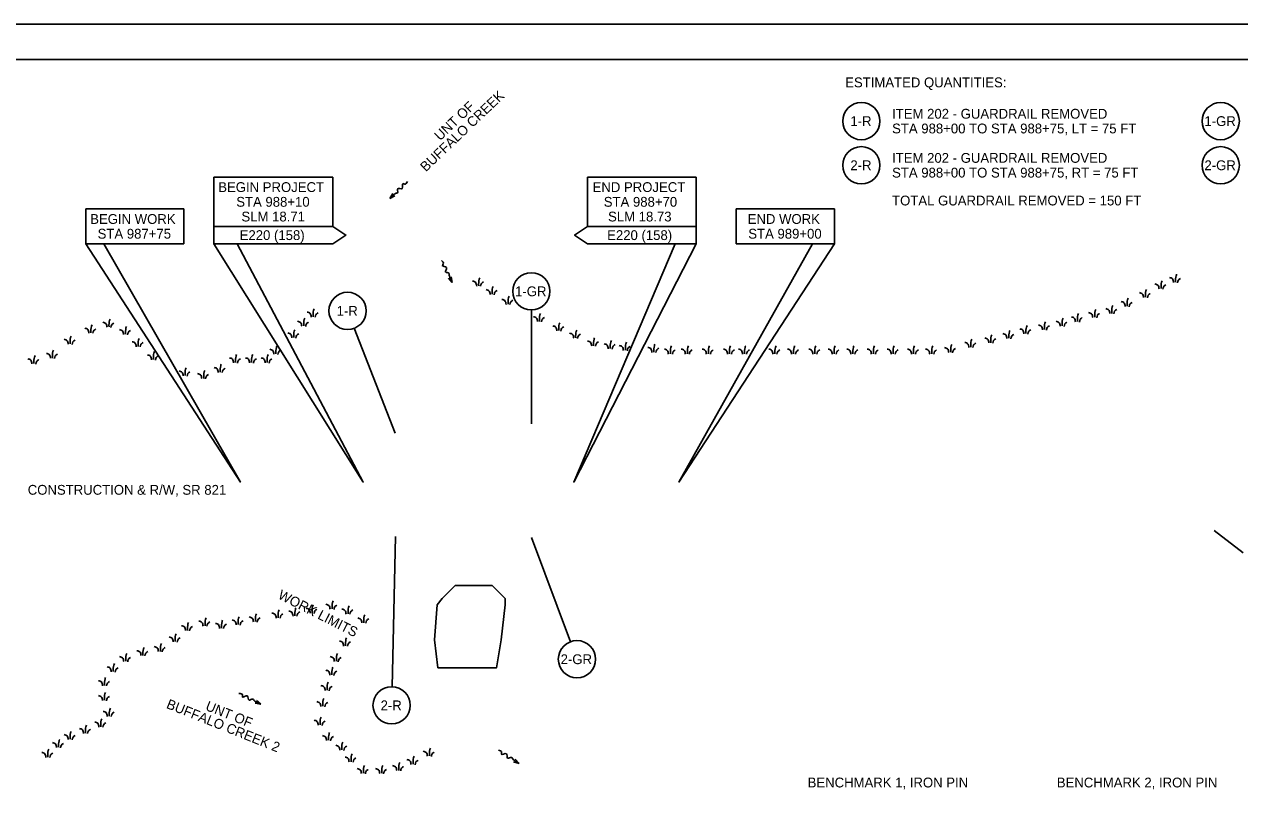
# Model space of a CAD drawing. Extents: x 0 to 905, y 0 to 440.
# Drawn here: x 207.4 to 553.9, y 221.7 to 440 of the extents above; entities that cross this region are included whole.
import ezdxf

# ---------------------------------------------------------------- set-up
doc = ezdxf.new("R2010")
doc.units = 0
for name, color, linetype in [('DR_X_Culvert', 7, 'Continuous'), ('DT_P_Slope_Break_Line', 7, 'Continuous'), ('GE_X_Alignment', 7, 'Continuous'), ('GE_X_Alignment_100_Cardinal_Points', 7, 'Continuous'), ('PF_X_Ground_Line', 7, 'Continuous'), ('PV_P_EOP', 7, 'Continuous'), ('TX_X_20', 7, 'Continuous')]:
    doc.layers.add(name, color=color, linetype=linetype)

msp = doc.modelspace()

# ---------------------------------------------------------------- linework, layer by layer
at = {"layer": 'DR_X_Culvert'}
msp.add_lwpolyline([(0, 0), (680, 0), (680, 440), (0, 440)], close=True, dxfattribs=at)
at = {"layer": 'DT_P_Slope_Break_Line'}
for p, q in [((312.42, 391.7), (311.58, 390.28)), ((311.58, 390.28), (313.02, 391.09)), ((328.3, 367.57), (329.37, 366.31)), ((329.37, 366.31), (329.07, 367.94)), ((273.21, 246.36), (274.84, 246.04)), ((274.84, 246.04), (273.59, 247.13)), ((346.85, 229.65), (348.43, 229.15)), ((348.43, 229.15), (347.31, 230.37))]:
    msp.add_line(p, q, dxfattribs=at)
for points in [[(311.58, 390.28), (312.77, 391.43), (313.35, 391.79), (313.75, 391.97), (313.84, 393.09), (315.11, 393.18), (315.34, 394.55), (315.81, 394.39), (316.59, 395.17)], [(329.37, 366.31), (328.66, 367.81), (328.51, 368.47), (328.46, 368.91), (327.43, 369.36), (327.76, 370.59), (326.53, 371.24), (326.83, 371.64), (326.35, 372.63)], [(274.84, 246.04), (273.35, 246.78), (272.83, 247.2), (272.52, 247.52), (271.43, 247.24), (270.93, 248.41), (269.56, 248.16), (269.55, 248.66), (268.56, 249.14)], [(348.43, 229.15), (347.03, 230.05), (346.56, 230.53), (346.28, 230.87), (345.17, 230.71), (344.8, 231.93), (343.41, 231.83), (343.46, 232.33), (342.53, 232.91)]]:
    msp.add_spline(points, degree=3, dxfattribs=at)
at = {"layer": 'GE_X_Alignment'}
for p, q in [((261.37, 377.36), (261.37, 396.36)), ((261.37, 396.36), (295.37, 396.36)), ((295.37, 382.36), (295.37, 396.36)), ((367.95, 382.36), (367.95, 396.36)), ((398.95, 396.36), (367.95, 396.36)), ((398.95, 377.36), (398.95, 396.36)), ((224.87, 377.36), (224.87, 387.36)), ((224.87, 387.36), (252.87, 387.36)), ((252.87, 377.36), (252.87, 387.36)), ((410.37, 377.36), (410.37, 387.36)), ((410.37, 387.36), (438.37, 387.36)), ((438.37, 377.36), (438.37, 387.36)), ((261.37, 382.36), (295.37, 382.36)), ((398.95, 382.36), (367.95, 382.36)), ((224.87, 377.36), (252.87, 377.36)), ((261.37, 377.36), (295.37, 377.36)), ((398.95, 377.36), (367.95, 377.36)), ((410.37, 377.36), (438.37, 377.36)), ((546.66, 295.61), (554.87, 289.22))]:
    msp.add_line(p, q, dxfattribs=at)
for points in [[(295.37, 382.36), (299.06, 379.86), (295.37, 377.36)], [(367.95, 382.36), (364.26, 379.86), (367.95, 377.36)], [(224.87, 377.36), (269, 309.44), (230.07, 377.36)], [(261.37, 377.36), (304, 309.44), (268.08, 377.36)], [(398.95, 377.36), (364, 309.44), (392.96, 377.36)], [(438.37, 377.36), (394, 309.44), (432.1, 377.36)]]:
    msp.add_lwpolyline(points, dxfattribs=at)
for centre in [(446.03, 412.38), (548.5, 412.38), (446.03, 399.79), (548.5, 399.79), (351.93, 363.83), (299.53, 358.25), (364.93, 258.89), (312.08, 245.73)]:
    msp.add_circle(centre, 5.31, dxfattribs=at)
at = {"layer": 'GE_X_Alignment_100_Cardinal_Points'}
for p, q in [((351.93, 326.04), (351.93, 358.52)), ((301.45, 353.31), (313.06, 323.4)), ((312.2, 251.04), (313.22, 293.94)), ((363.07, 263.86), (351.98, 293.64))]:
    msp.add_line(p, q, dxfattribs=at)
at = {"layer": 'PF_X_Ground_Line'}
msp.add_lwpolyline([(30, 430), (670, 430), (670, 10), (30, 10)], close=True, dxfattribs=at)
at = {"layer": 'PV_P_EOP'}
msp.add_lwpolyline([(325.29, 256.44), (342.02, 256.44), (343.29, 264.44), (344.42, 274.44), (344.49, 276.19), (340.75, 279.94), (330.25, 279.94), (326.51, 276.19), (325.08, 274.44), (324.31, 264.44), (325.29, 256.44)], close=True, dxfattribs=at)
at = {"layer": 'TX_X_20'}
for points in [[(336.91, 365.42), (336.91, 366.37), (337.02, 367.26), (337.2, 367.67)], [(533.89, 367.77), (534.72, 367.42), (535.07, 366.35)], [(535.64, 366.43), (535.64, 367.38), (535.76, 368.27), (535.93, 368.68)], [(536.19, 366.29), (536.43, 367.06), (537.02, 367.53)], [(335.16, 366.76), (335.99, 366.41), (336.34, 365.34)], [(337.46, 365.28), (337.7, 366.05), (338.29, 366.52)], [(339.03, 364.34), (339.85, 363.99), (340.21, 362.92)], [(340.77, 363), (340.77, 363.95), (340.89, 364.84), (341.07, 365.25)], [(341.33, 362.86), (341.56, 363.63), (342.15, 364.1)], [(527.04, 362.13), (527.04, 363.08), (527.16, 363.96), (527.33, 364.38)], [(529.73, 365.94), (530.56, 365.58), (530.92, 364.52)], [(531.48, 364.6), (531.48, 365.54), (531.6, 366.43), (531.77, 366.85)], [(532.03, 364.45), (532.27, 365.22), (532.86, 365.7)], [(343.54, 361.52), (344.36, 361.17), (344.72, 360.1)], [(345.28, 360.18), (345.28, 361.13), (345.4, 362.02), (345.58, 362.43)], [(345.84, 360.04), (346.07, 360.81), (346.66, 361.28)], [(520.08, 360.93), (520.91, 360.58), (521.26, 359.51)], [(521.82, 359.59), (521.82, 360.54), (521.94, 361.42), (522.12, 361.84)], [(522.38, 359.45), (522.62, 360.21), (523.21, 360.69)], [(525.29, 363.47), (526.12, 363.12), (526.48, 362.05)], [(527.59, 361.99), (527.83, 362.75), (528.42, 363.23)], [(287.99, 357.91), (288.81, 357.56), (289.17, 356.49)], [(289.73, 356.57), (289.73, 357.52), (289.85, 358.4), (290.03, 358.82)], [(290.29, 356.43), (290.52, 357.19), (291.11, 357.67)], [(354.26, 355.26), (354.26, 356.21), (354.38, 357.1), (354.56, 357.51)], [(507.65, 355.23), (507.65, 356.17), (507.77, 357.06), (507.94, 357.48)], [(510.83, 357.76), (511.66, 357.41), (512.02, 356.34)], [(512.58, 356.42), (512.58, 357.37), (512.7, 358.26), (512.88, 358.67)], [(513.14, 356.28), (513.37, 357.05), (513.96, 357.52)], [(515.7, 358.89), (516.53, 358.54), (516.88, 357.47)], [(517.44, 357.55), (517.44, 358.5), (517.56, 359.39), (517.74, 359.8)], [(518, 357.41), (518.24, 358.18), (518.83, 358.65)], [(226.37, 351.99), (226.37, 352.94), (226.48, 353.82), (226.66, 354.24)], [(229.76, 355.02), (230.59, 354.67), (230.95, 353.6)], [(231.51, 353.68), (231.51, 354.63), (231.63, 355.52), (231.81, 355.93)], [(232.07, 353.54), (232.3, 354.31), (232.89, 354.78)], [(236.23, 351.57), (236.23, 352.51), (236.35, 353.4), (236.53, 353.82)], [(285.29, 355.29), (286.12, 354.94), (286.47, 353.87)], [(287.03, 353.95), (287.03, 354.9), (287.15, 355.78), (287.33, 356.2)], [(287.59, 353.81), (287.83, 354.57), (288.42, 355.05)], [(352.52, 356.6), (353.35, 356.25), (353.7, 355.18)], [(354.82, 355.12), (355.06, 355.89), (355.65, 356.36)], [(358.04, 353.98), (358.86, 353.63), (359.22, 352.56)], [(359.78, 352.64), (359.78, 353.59), (359.9, 354.48), (360.08, 354.89)], [(360.34, 352.5), (360.57, 353.27), (361.16, 353.74)], [(492.96, 351.79), (492.96, 352.74), (493.08, 353.63), (493.26, 354.04)], [(496.5, 354.26), (497.33, 353.91), (497.68, 352.84)], [(498.25, 352.92), (498.25, 353.87), (498.37, 354.75), (498.54, 355.17)], [(498.8, 352.78), (499.04, 353.54), (499.63, 354.02)], [(501.53, 355.3), (502.36, 354.94), (502.71, 353.88)], [(503.28, 353.96), (503.28, 354.9), (503.4, 355.79), (503.57, 356.21)], [(503.83, 353.81), (504.07, 354.58), (504.66, 355.06)], [(505.9, 356.57), (506.73, 356.21), (507.08, 355.15)], [(508.2, 355.08), (508.44, 355.85), (509.03, 356.33)], [(218.7, 350.15), (219.53, 349.8), (219.88, 348.73)], [(220.45, 348.81), (220.45, 349.76), (220.56, 350.65), (220.74, 351.06)], [(224.62, 353.33), (225.45, 352.98), (225.8, 351.91)], [(226.92, 351.85), (227.16, 352.61), (227.75, 353.09)], [(234.49, 352.91), (235.32, 352.55), (235.67, 351.49)], [(236.79, 351.42), (237.03, 352.19), (237.62, 352.67)], [(239.83, 348.11), (239.83, 349.06), (239.95, 349.94), (240.12, 350.36)], [(282.47, 351.98), (283.3, 351.63), (283.65, 350.56)], [(284.22, 350.64), (284.22, 351.59), (284.33, 352.48), (284.51, 352.89)], [(284.77, 350.5), (285.01, 351.27), (285.6, 351.74)], [(362.83, 351.89), (363.66, 351.54), (364.01, 350.47)], [(364.57, 350.55), (364.57, 351.5), (364.69, 352.38), (364.87, 352.8)], [(365.13, 350.41), (365.37, 351.17), (365.96, 351.65)], [(369.69, 348.33), (369.69, 349.28), (369.81, 350.17), (369.98, 350.58)], [(477.24, 347.91), (477.24, 348.86), (477.36, 349.75), (477.54, 350.16)], [(481.21, 350.52), (482.03, 350.17), (482.39, 349.1)], [(482.95, 349.18), (482.95, 350.13), (483.07, 351.02), (483.25, 351.43)], [(483.51, 349.04), (483.74, 349.81), (484.33, 350.28)], [(486.35, 351.79), (487.18, 351.44), (487.53, 350.37)], [(488.1, 350.45), (488.1, 351.4), (488.22, 352.29), (488.39, 352.7)], [(488.65, 350.31), (488.89, 351.08), (489.48, 351.55)], [(491.21, 353.13), (492.04, 352.78), (492.4, 351.71)], [(493.52, 351.65), (493.75, 352.42), (494.34, 352.89)], [(215.4, 344.8), (215.4, 345.74), (215.52, 346.63), (215.69, 347.05)], [(221, 348.67), (221.24, 349.44), (221.83, 349.91)], [(238.08, 349.45), (238.91, 349.1), (239.26, 348.03)], [(240.38, 347.97), (240.62, 348.73), (241.21, 349.21)], [(244.2, 344.37), (244.2, 345.32), (244.32, 346.21), (244.49, 346.62)], [(277.35, 347.31), (278.18, 346.95), (278.54, 345.89)], [(279.1, 345.97), (279.1, 346.91), (279.22, 347.8), (279.4, 348.22)], [(279.66, 345.82), (279.89, 346.59), (280.48, 347.07)], [(367.94, 349.67), (368.77, 349.32), (369.13, 348.25)], [(370.24, 348.19), (370.48, 348.96), (371.07, 349.43)], [(372.7, 348.87), (373.52, 348.51), (373.88, 347.45)], [(374.44, 347.53), (374.44, 348.47), (374.56, 349.36), (374.74, 349.78)], [(375, 347.38), (375.23, 348.15), (375.82, 348.63)], [(377, 348.38), (377.83, 348.03), (378.19, 346.96)], [(378.75, 347.04), (378.75, 347.99), (378.87, 348.88), (379.05, 349.29)], [(379.31, 346.9), (379.54, 347.67), (380.13, 348.14)], [(385.14, 347.83), (385.97, 347.48), (386.32, 346.41)], [(386.88, 346.49), (386.88, 347.44), (387, 348.33), (387.18, 348.74)], [(387.44, 346.35), (387.68, 347.12), (388.27, 347.59)], [(389.85, 347.35), (390.68, 346.99), (391.03, 345.93)], [(391.6, 346.01), (391.6, 346.95), (391.72, 347.84), (391.89, 348.26)], [(392.15, 345.86), (392.39, 346.63), (392.98, 347.11)], [(394.68, 347.35), (395.51, 346.99), (395.87, 345.93)], [(396.43, 346.01), (396.43, 346.95), (396.55, 347.84), (396.72, 348.26)], [(396.98, 345.86), (397.22, 346.63), (397.81, 347.11)], [(400.68, 347.35), (401.51, 346.99), (401.87, 345.93)], [(402.43, 346.01), (402.43, 346.95), (402.55, 347.84), (402.73, 348.26)], [(402.99, 345.86), (403.22, 346.63), (403.81, 347.11)], [(406.69, 347.35), (407.51, 346.99), (407.87, 345.93)], [(408.43, 346.01), (408.43, 346.95), (408.55, 347.84), (408.73, 348.26)], [(408.99, 345.86), (409.22, 346.63), (409.81, 347.11)], [(410.99, 347.35), (411.82, 346.99), (412.18, 345.93)], [(412.74, 346.01), (412.74, 346.95), (412.86, 347.84), (413.04, 348.26)], [(413.3, 345.86), (413.53, 346.63), (414.12, 347.11)], [(419.65, 347.35), (420.48, 346.99), (420.84, 345.93)], [(421.4, 346.01), (421.4, 346.95), (421.52, 347.84), (421.7, 348.26)], [(421.96, 345.86), (422.19, 346.63), (422.78, 347.11)], [(424.97, 347.35), (425.8, 346.99), (426.15, 345.93)], [(426.72, 346.01), (426.72, 346.95), (426.84, 347.84), (427.01, 348.26)], [(427.27, 345.86), (427.51, 346.63), (428.1, 347.11)], [(431.03, 347.35), (431.85, 346.99), (432.21, 345.93)], [(432.77, 346.01), (432.77, 346.95), (432.89, 347.84), (433.07, 348.26)], [(433.33, 345.86), (433.56, 346.63), (434.15, 347.11)], [(436.52, 347.35), (437.35, 346.99), (437.71, 345.93)], [(438.27, 346.01), (438.27, 346.95), (438.39, 347.84), (438.57, 348.26)], [(438.83, 345.86), (439.06, 346.63), (439.65, 347.11)], [(441.88, 347.35), (442.71, 346.99), (443.06, 345.93)], [(443.63, 346.01), (443.63, 346.95), (443.75, 347.84), (443.92, 348.26)], [(444.18, 345.86), (444.42, 346.63), (445.01, 347.11)], [(447.73, 347.35), (448.56, 346.99), (448.91, 345.93)], [(449.48, 346.01), (449.48, 346.95), (449.6, 347.84), (449.77, 348.26)], [(450.03, 345.86), (450.27, 346.63), (450.86, 347.11)], [(453.37, 347.35), (454.2, 346.99), (454.55, 345.93)], [(455.12, 346.01), (455.12, 346.95), (455.23, 347.84), (455.41, 348.26)], [(455.67, 345.86), (455.91, 346.63), (456.5, 347.11)], [(459.15, 347.35), (459.98, 346.99), (460.33, 345.93)], [(460.89, 346.01), (460.89, 346.95), (461.01, 347.84), (461.19, 348.26)], [(461.45, 345.86), (461.69, 346.63), (462.28, 347.11)], [(464.36, 347.35), (465.19, 346.99), (465.55, 345.93)], [(466.11, 346.01), (466.11, 346.95), (466.23, 347.84), (466.41, 348.26)], [(466.67, 345.86), (466.9, 346.63), (467.49, 347.11)], [(469.76, 347.78), (470.59, 347.43), (470.94, 346.36)], [(471.51, 346.44), (471.51, 347.39), (471.62, 348.27), (471.8, 348.69)], [(472.06, 346.3), (472.3, 347.06), (472.89, 347.54)], [(475.5, 349.25), (476.33, 348.9), (476.68, 347.83)], [(477.8, 347.77), (478.04, 348.54), (478.63, 349.01)], [(208.37, 344.58), (209.19, 344.23), (209.55, 343.16)], [(210.11, 343.24), (210.11, 344.19), (210.23, 345.08), (210.41, 345.49)], [(210.67, 343.1), (210.9, 343.87), (211.49, 344.34)], [(213.65, 346.14), (214.48, 345.78), (214.84, 344.72)], [(215.95, 344.65), (216.19, 345.42), (216.78, 345.9)], [(242.45, 345.71), (243.28, 345.36), (243.63, 344.29)], [(244.75, 344.23), (244.99, 345), (245.58, 345.47)], [(265.85, 344.86), (266.68, 344.51), (267.03, 343.44)], [(267.6, 343.52), (267.6, 344.47), (267.72, 345.36), (267.89, 345.77)], [(268.15, 343.38), (268.39, 344.15), (268.98, 344.62)], [(270.43, 344.86), (271.25, 344.51), (271.61, 343.44)], [(272.17, 343.52), (272.17, 344.47), (272.29, 345.36), (272.47, 345.77)], [(272.73, 343.38), (272.96, 344.15), (273.55, 344.62)], [(274.86, 344.86), (275.68, 344.51), (276.04, 343.44)], [(276.6, 343.52), (276.6, 344.47), (276.72, 345.36), (276.9, 345.77)], [(277.16, 343.38), (277.39, 344.15), (277.98, 344.62)], [(251.47, 341.13), (252.3, 340.77), (252.66, 339.71)], [(253.22, 339.79), (253.22, 340.73), (253.34, 341.62), (253.51, 342.04)], [(253.77, 339.64), (254.01, 340.41), (254.6, 340.89)], [(256.76, 340.35), (257.59, 340), (257.94, 338.93)], [(258.51, 339.01), (258.51, 339.96), (258.62, 340.85), (258.8, 341.26)], [(259.06, 338.87), (259.3, 339.64), (259.89, 340.11)], [(261.48, 342.11), (262.31, 341.76), (262.66, 340.69)], [(263.23, 340.77), (263.23, 341.72), (263.35, 342.61), (263.52, 343.02)], [(263.78, 340.63), (264.02, 341.4), (264.61, 341.87)], [(289.43, 272.11), (289.43, 273.06), (289.54, 273.94), (289.72, 274.36)], [(293.37, 274.59), (294.2, 274.23), (294.55, 273.17)], [(295.11, 273.25), (295.11, 274.19), (295.23, 275.08), (295.41, 275.5)], [(295.67, 273.1), (295.91, 273.87), (296.5, 274.35)], [(299.66, 271.85), (299.66, 272.79), (299.78, 273.68), (299.96, 274.1)], [(258.89, 268.42), (258.89, 269.37), (259.01, 270.26), (259.18, 270.67)], [(268.35, 268.77), (268.35, 269.72), (268.47, 270.61), (268.65, 271.02)], [(271.49, 270.97), (272.32, 270.62), (272.67, 269.55)], [(273.24, 269.63), (273.24, 270.58), (273.35, 271.47), (273.53, 271.88)], [(273.79, 269.49), (274.03, 270.26), (274.62, 270.73)], [(277.98, 272.06), (278.81, 271.7), (279.17, 270.64)], [(279.73, 270.72), (279.73, 271.66), (279.85, 272.55), (280.03, 272.97)], [(280.29, 270.57), (280.52, 271.34), (281.11, 271.82)], [(282.78, 272.62), (283.61, 272.27), (283.97, 271.2)], [(284.53, 271.28), (284.53, 272.23), (284.65, 273.12), (284.82, 273.53)], [(285.08, 271.14), (285.32, 271.91), (285.91, 272.38)], [(287.68, 273.45), (288.51, 273.1), (288.86, 272.03)], [(289.98, 271.97), (290.22, 272.73), (290.81, 273.21)], [(297.92, 273.19), (298.75, 272.83), (299.1, 271.77)], [(300.22, 271.7), (300.46, 272.47), (301.05, 272.95)], [(302.42, 270.65), (303.25, 270.29), (303.61, 269.23)], [(304.17, 269.31), (304.17, 270.25), (304.29, 271.14), (304.46, 271.56)], [(304.72, 269.16), (304.96, 269.93), (305.55, 270.41)], [(252.17, 268.46), (252.99, 268.11), (253.35, 267.04)], [(253.91, 267.12), (253.91, 268.07), (254.03, 268.95), (254.21, 269.37)], [(254.47, 266.98), (254.7, 267.74), (255.29, 268.22)], [(257.14, 269.76), (257.97, 269.41), (258.33, 268.34)], [(259.44, 268.28), (259.68, 269.05), (260.27, 269.52)], [(261.87, 269.12), (262.7, 268.76), (263.06, 267.7)], [(263.62, 267.78), (263.62, 268.72), (263.74, 269.61), (263.91, 270.03)], [(264.17, 267.63), (264.41, 268.4), (265, 268.88)], [(266.61, 270.11), (267.43, 269.76), (267.79, 268.69)], [(268.91, 268.63), (269.14, 269.4), (269.73, 269.87)], [(246.15, 261.14), (246.15, 262.09), (246.27, 262.97), (246.45, 263.39)], [(248.64, 265.24), (249.47, 264.89), (249.83, 263.82)], [(250.39, 263.9), (250.39, 264.85), (250.51, 265.74), (250.69, 266.15)], [(250.95, 263.76), (251.18, 264.53), (251.77, 265)], [(297.22, 264.08), (298.05, 263.73), (298.4, 262.66)], [(298.96, 262.74), (298.96, 263.69), (299.08, 264.57), (299.26, 264.99)], [(299.52, 262.6), (299.76, 263.36), (300.35, 263.84)], [(236.28, 258.3), (236.28, 259.25), (236.39, 260.14), (236.57, 260.55)], [(239.46, 261.33), (240.29, 260.98), (240.64, 259.91)], [(241.2, 259.99), (241.2, 260.94), (241.32, 261.83), (241.5, 262.24)], [(241.76, 259.85), (242, 260.62), (242.59, 261.09)], [(244.41, 262.48), (245.23, 262.13), (245.59, 261.06)], [(246.71, 261), (246.94, 261.76), (247.53, 262.24)], [(296.34, 258.32), (296.34, 259.26), (296.46, 260.15), (296.63, 260.57)], [(230.99, 256.72), (231.82, 256.37), (232.17, 255.3)], [(232.74, 255.38), (232.74, 256.33), (232.85, 257.22), (233.03, 257.63)], [(233.29, 255.24), (233.53, 256.01), (234.12, 256.48)], [(234.53, 259.64), (235.36, 259.29), (235.71, 258.22)], [(236.83, 258.16), (237.07, 258.93), (237.66, 259.4)], [(294.59, 259.66), (295.42, 259.3), (295.78, 258.24)], [(295.07, 254.42), (295.07, 255.37), (295.19, 256.26), (295.37, 256.67)], [(296.89, 258.17), (297.13, 258.94), (297.72, 259.42)], [(230.26, 251.41), (230.26, 252.36), (230.37, 253.25), (230.55, 253.66)], [(293.32, 255.76), (294.15, 255.41), (294.51, 254.34)], [(295.63, 254.28), (295.86, 255.05), (296.45, 255.52)], [(228.51, 252.75), (229.34, 252.4), (229.69, 251.33)], [(230.81, 251.27), (231.05, 252.04), (231.64, 252.51)], [(291.95, 251.4), (292.78, 251.05), (293.14, 249.98)], [(293.7, 250.06), (293.7, 251.01), (293.82, 251.89), (294, 252.31)], [(294.26, 249.92), (294.49, 250.68), (295.08, 251.16)], [(228.48, 248.53), (229.31, 248.18), (229.66, 247.11)], [(230.23, 247.19), (230.23, 248.14), (230.35, 249.03), (230.52, 249.44)], [(230.78, 247.05), (231.02, 247.82), (231.61, 248.29)], [(290.73, 246.8), (291.56, 246.45), (291.91, 245.38)], [(292.48, 245.46), (292.48, 246.41), (292.59, 247.3), (292.77, 247.71)], [(293.03, 245.32), (293.27, 246.09), (293.86, 246.56)], [(229.84, 244.01), (230.67, 243.65), (231.03, 242.59)], [(231.59, 242.67), (231.59, 243.61), (231.71, 244.5), (231.89, 244.92)], [(232.15, 242.52), (232.38, 243.29), (232.97, 243.77)], [(223.08, 239.14), (223.91, 238.79), (224.26, 237.72)], [(224.82, 237.8), (224.82, 238.75), (224.94, 239.63), (225.12, 240.05)], [(227.45, 240.97), (228.28, 240.62), (228.63, 239.55)], [(229.19, 239.63), (229.19, 240.58), (229.31, 241.47), (229.49, 241.88)], [(229.75, 239.49), (229.99, 240.26), (230.58, 240.73)], [(289.98, 241.5), (290.81, 241.15), (291.17, 240.08)], [(291.73, 240.16), (291.73, 241.11), (291.85, 242), (292.03, 242.41)], [(292.29, 240.02), (292.52, 240.79), (293.11, 241.26)], [(217.14, 233.78), (217.14, 234.73), (217.26, 235.61), (217.44, 236.03)], [(218.71, 237.38), (219.54, 237.02), (219.89, 235.96)], [(220.45, 236.04), (220.45, 236.98), (220.57, 237.87), (220.75, 238.29)], [(221.01, 235.89), (221.25, 236.66), (221.84, 237.14)], [(225.38, 237.66), (225.62, 238.42), (226.21, 238.9)], [(292.38, 237.11), (293.21, 236.75), (293.56, 235.69)], [(294.13, 235.77), (294.13, 236.71), (294.25, 237.6), (294.42, 238.02)], [(294.68, 235.62), (294.92, 236.39), (295.51, 236.87)], [(212.32, 232.32), (213.15, 231.96), (213.5, 230.9)], [(214.07, 230.98), (214.07, 231.92), (214.19, 232.81), (214.36, 233.23)], [(215.4, 235.12), (216.22, 234.77), (216.58, 233.7)], [(217.7, 233.64), (217.93, 234.4), (218.52, 234.88)], [(296.16, 234.35), (296.98, 234), (297.34, 232.93)], [(297.9, 233.01), (297.9, 233.96), (298.02, 234.85), (298.2, 235.26)], [(298.46, 232.87), (298.69, 233.64), (299.28, 234.11)], [(321.12, 232.63), (321.95, 232.27), (322.3, 231.21)], [(322.87, 231.29), (322.87, 232.23), (322.98, 233.12), (323.16, 233.54)], [(323.42, 231.14), (323.66, 231.91), (324.25, 232.39)], [(214.62, 230.83), (214.86, 231.6), (215.45, 232.08)], [(298.8, 231), (299.63, 230.65), (299.98, 229.58)], [(300.55, 229.66), (300.55, 230.61), (300.67, 231.5), (300.84, 231.91)], [(301.1, 229.52), (301.34, 230.29), (301.93, 230.76)], [(314.13, 227.19), (314.13, 228.14), (314.25, 229.03), (314.42, 229.44)], [(316.47, 230.3), (317.3, 229.94), (317.65, 228.88)], [(318.21, 228.96), (318.21, 229.9), (318.33, 230.79), (318.51, 231.21)], [(318.77, 228.81), (319.01, 229.58), (319.6, 230.06)], [(302.3, 227.69), (303.13, 227.33), (303.48, 226.27)], [(304.05, 226.35), (304.05, 227.29), (304.17, 228.18), (304.34, 228.6)], [(304.6, 226.2), (304.84, 226.97), (305.43, 227.45)], [(307.52, 227.69), (308.35, 227.33), (308.7, 226.27)], [(309.26, 226.35), (309.26, 227.29), (309.38, 228.18), (309.56, 228.6)], [(309.82, 226.2), (310.06, 226.97), (310.65, 227.45)], [(312.38, 228.53), (313.21, 228.18), (313.56, 227.11)], [(314.68, 227.05), (314.92, 227.82), (315.51, 228.29)]]:
    msp.add_spline(points, degree=3, dxfattribs=at)

# ---------------------------------------------------------------- texts
at = {"layer": 'GE_X_Alignment'}
for s, p in [('ESTIMATED QUANTITIES:', (441.42, 422.03)), ('ITEM 202 - GUARDRAIL REMOVED', (454.79, 413.08)), ('1-R', (442.9, 410.98)), ('1-GR', (543.85, 410.98)), ('STA 988+00 TO STA 988+75, LT = 75 FT', (454.79, 408.88)), ('ITEM 202 - GUARDRAIL REMOVED', (454.79, 400.49)), ('2-R', (442.9, 398.39)), ('STA 988+00 TO STA 988+75, RT = 75 FT', (454.79, 396.29)), ('2-GR', (543.85, 398.39)), ('BEGIN PROJECT', (262.65, 392.16)), ('END PROJECT', (369.4, 392.16)), ('STA 988+10', (267.79, 387.96)), ('STA 988+70', (372.58, 387.96)), ('TOTAL GUARDRAIL REMOVED = 150 FT', (454.79, 388.33)), ('BEGIN WORK', (226.15, 383.06)), ('SLM 18.71', (269.27, 383.76)), ('SLM 18.73', (373.8, 383.76)), ('END WORK', (413.62, 383.06)), ('STA 987+75', (228.27, 378.86)), ('E220 (158)', (268.77, 378.46)), ('E220 (158)', (373.55, 378.46)), ('STA 989+00', (413.79, 378.86)), ('1-GR', (347.29, 362.43)), ('1-R', (296.41, 356.85)), ('2-GR', (360.28, 257.49)), ('2-R', (308.95, 244.33)), ('BENCHMARK 1, IRON PIN', (430.71, 222.32)), ('BENCHMARK 2, IRON PIN', (501.76, 222.32))]:
    msp.add_text(s, height=2.8, dxfattribs=at).set_placement(p)
for s, rotation, p in [('BUFFALO CREEK', 43.5838, (321.85, 397.77)), ('UNT OF', 43.5838, (325.9, 406.62)), (' CONSTRUCTION & R/W, SR 821', 360, (207.3, 305.81)), ('WORK LIMITS', 333.0824, (279.46, 276.32)), ('BUFFALO CREEK 2', 338.2331, (247.64, 245.02)), ('UNT OF', 338.2331, (258.8, 244.47))]:
    msp.add_text(s, height=2.8, rotation=rotation, dxfattribs=at).set_placement(p)

doc.saveas('drawing.dxf')
